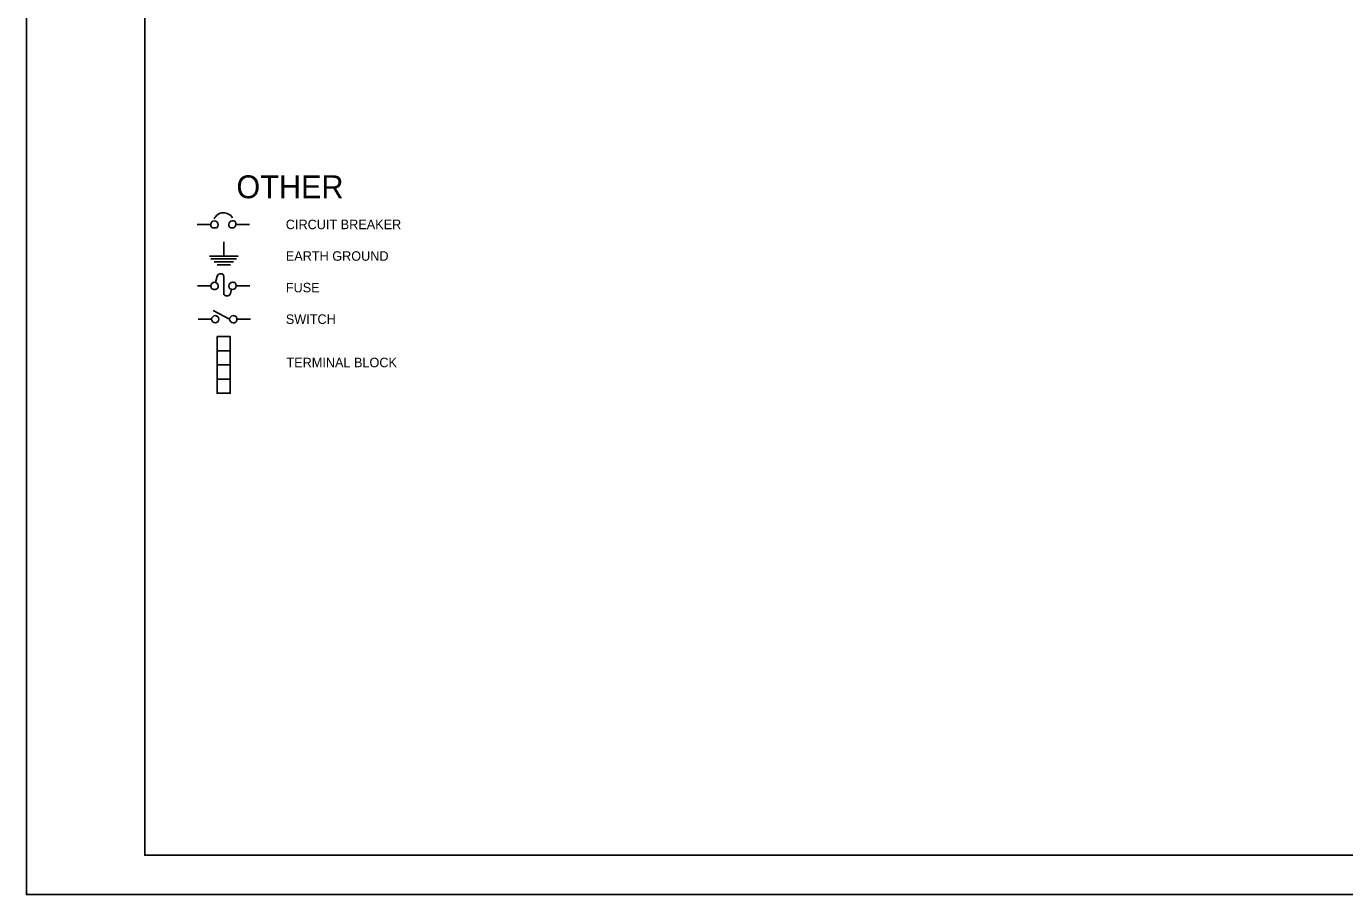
# Model space of a CAD drawing. Extents: x 1299104.8 to 1299141.6, y 239639.8 to 239661.8.
# Drawn here: x 1299104.8 to 1299121.51, y 239639.79 to 239650.79 of the extents above; entities that cross this region are included whole.
import ezdxf

# ---------------------------------------------------------------- set-up
doc = ezdxf.new("R2010")
doc.units = 0
for name, color, linetype in [('DIM TXT', 7, 'Continuous'), ('GS_noplot_1', 7, 'Continuous'), ('Level 1', 7, 'Continuous')]:
    doc.layers.add(name, color=color, linetype=linetype)

msp = doc.modelspace()

# ---------------------------------------------------------------- linework, layer by layer
at = {"layer": 'DIM TXT'}
for points in [[(1299106.967, 239648.282), (1299107.139, 239648.282)], [(1299107.457, 239648.282), (1299107.631, 239648.282)], [(1299107.303, 239647.882), (1299107.303, 239648.063)], [(1299107.121, 239647.882), (1299107.485, 239647.882)], [(1299107.141, 239647.846), (1299107.464, 239647.846)], [(1299107.18, 239647.81), (1299107.426, 239647.81)], [(1299107.22, 239647.772), (1299107.387, 239647.772)], [(1299107.141, 239647.504), (1299106.969, 239647.504)], [(1299107.199, 239647.548), (1299107.22, 239647.626)], [(1299107.303, 239647.418), (1299107.303, 239647.615)], [(1299107.633, 239647.504), (1299107.459, 239647.504)], [(1299107.388, 239647.406), (1299107.402, 239647.461)], [(1299107.377, 239647.08), (1299107.168, 239647.19)], [(1299107.15, 239647.08), (1299106.977, 239647.08)], [(1299107.468, 239647.08), (1299107.641, 239647.08)]]:
    msp.add_lwpolyline(points, dxfattribs=at)
for points in [[(1299107.219, 239646.862), (1299107.219, 239646.682), (1299107.385, 239646.682), (1299107.385, 239646.862)], [(1299107.219, 239646.502), (1299107.219, 239646.682), (1299107.385, 239646.682), (1299107.385, 239646.502)], [(1299107.219, 239646.323), (1299107.219, 239646.502), (1299107.385, 239646.502), (1299107.385, 239646.323)], [(1299107.219, 239646.323), (1299107.219, 239646.143), (1299107.385, 239646.143), (1299107.385, 239646.323)]]:
    msp.add_lwpolyline(points, close=True, dxfattribs=at)
for centre, radius, start, end in [((1299107.302, 239648.297), 0.133, 93.2982, 155.0557), ((1299107.303, 239648.299), 0.13, 30.5418, 93.7242), ((1299107.185, 239648.281), 0.0462, 90.502, 179.498), ((1299107.185, 239648.281), 0.0462, 0.502, 89.498), ((1299107.413, 239648.281), 0.0462, 90.502, 179.498), ((1299107.413, 239648.281), 0.0439, 269.2527, 0.7473), ((1299107.187, 239647.503), 0.0462, 90.502, 179.498), ((1299107.187, 239647.503), 0.0462, 90.502, 179.498), ((1299107.186, 239647.503), 0.0462, 0.502, 89.498), ((1299107.186, 239647.503), 0.0462, 0.502, 89.498), ((1299107.262, 239647.615), 0.0429, 82.4498, 165.7046), ((1299107.415, 239647.503), 0.0462, 90.502, 179.498), ((1299107.415, 239647.503), 0.0462, 90.502, 179.498), ((1299107.415, 239647.503), 0.0439, 269.2527, 0.7473), ((1299107.415, 239647.503), 0.0439, 269.2527, 0.7473), ((1299107.347, 239647.419), 0.0432, 262.324, 343.4865), ((1299107.196, 239647.08), 0.0462, 90.502, 179.498), ((1299107.196, 239647.081), 0.0462, 180.502, 269.498), ((1299107.195, 239647.08), 0.0462, 0.502, 89.498), ((1299107.195, 239647.081), 0.0462, 270.502, 359.498), ((1299107.424, 239647.08), 0.0462, 90.502, 179.498), ((1299107.424, 239647.081), 0.0462, 180.502, 269.498)]:
    msp.add_arc(centre, radius, start, end, dxfattribs=at)
for points in [[(1299107.139, 239648.282), (1299107.139, 239648.257), (1299107.16, 239648.237), (1299107.185, 239648.237)], [(1299107.185, 239648.237), (1299107.21, 239648.237), (1299107.231, 239648.257), (1299107.231, 239648.282)], [(1299107.367, 239648.282), (1299107.367, 239648.257), (1299107.388, 239648.237), (1299107.413, 239648.237)], [(1299107.457, 239648.282), (1299107.457, 239648.307), (1299107.438, 239648.328), (1299107.413, 239648.328)], [(1299107.141, 239647.504), (1299107.141, 239647.479), (1299107.162, 239647.459), (1299107.187, 239647.459)], [(1299107.141, 239647.504), (1299107.141, 239647.479), (1299107.162, 239647.459), (1299107.187, 239647.459)], [(1299107.187, 239647.459), (1299107.212, 239647.459), (1299107.233, 239647.479), (1299107.233, 239647.504)], [(1299107.187, 239647.459), (1299107.212, 239647.459), (1299107.233, 239647.479), (1299107.233, 239647.504)], [(1299107.303, 239647.615), (1299107.303, 239647.637), (1299107.288, 239647.655), (1299107.267, 239647.658)], [(1299107.369, 239647.504), (1299107.369, 239647.479), (1299107.39, 239647.459), (1299107.415, 239647.459)], [(1299107.369, 239647.504), (1299107.369, 239647.479), (1299107.39, 239647.459), (1299107.415, 239647.459)], [(1299107.459, 239647.504), (1299107.459, 239647.529), (1299107.44, 239647.549), (1299107.415, 239647.549)], [(1299107.459, 239647.504), (1299107.459, 239647.529), (1299107.44, 239647.549), (1299107.415, 239647.549)], [(1299107.303, 239647.418), (1299107.303, 239647.397), (1299107.32, 239647.379), (1299107.341, 239647.376)], [(1299107.468, 239647.08), (1299107.468, 239647.105), (1299107.448, 239647.126), (1299107.423, 239647.126)], [(1299107.423, 239647.035), (1299107.448, 239647.035), (1299107.468, 239647.055), (1299107.468, 239647.08)]]:
    msp.add_open_spline(points, degree=2, dxfattribs=at)
at = {"layer": 'GS_noplot_1'}
msp.add_lwpolyline([(1299104.802, 239661.791), (1299138.802, 239661.791), (1299138.802, 239639.791), (1299104.802, 239639.791)], close=True, dxfattribs=at)
at = {"layer": 'Level 1'}
msp.add_lwpolyline([(1299138.302, 239640.291), (1299106.302, 239640.291), (1299106.302, 239661.291), (1299138.302, 239661.291)], close=True, dxfattribs=at)

# ---------------------------------------------------------------- texts
at = {"layer": 'DIM TXT'}
for s, height, p in [('OTHER', 0.29, (1299107.464, 239648.614)), ('CIRCUIT BREAKER', 0.12, (1299108.09, 239648.222)), ('EARTH GROUND', 0.12, (1299108.09, 239647.822)), ('FUSE', 0.12, (1299108.09, 239647.422)), ('SWITCH', 0.12, (1299108.09, 239647.022)), ('TERMINAL BLOCK', 0.12, (1299108.098, 239646.473))]:
    msp.add_text(s, height=height, dxfattribs=at).set_placement(p)

doc.saveas('drawing.dxf')
